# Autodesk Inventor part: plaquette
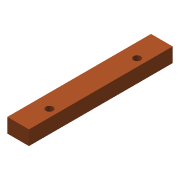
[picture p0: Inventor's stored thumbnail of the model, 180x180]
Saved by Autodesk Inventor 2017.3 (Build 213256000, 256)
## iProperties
Shininess: 20.0
Angle Display Precision: 2
Document Length Units: 11269
Document Angle Units: 11279
Document Time Units: 11290
Document Mass Units: 11283
Document Length Units Precision: 3
Document Angle Units Precision: 2
Created: 2002-04
Part Number: plaquette
Material: Générique
Document SubType Name: Modélisation
Designer: Administrateur
Density: 1 g/cm^3
Appearance: Orange (moyen)
Density: 0.0
Volumn: 0.0
Area: 0.0
PropertySet Name: Model Information
Control State: 0
Master: False
Checked Out: False
Author: Administrateur
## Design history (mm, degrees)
sketch "Esquisse1"
  geometry: L1 (-10, -0.25)-(-10, 99.25) reference; L2 (-25, 99.25)-(-10, 99.25) reference; L3 (-25, -0.25)-(-25, 99.25) reference; L4 (-10, -0.25)-(-25, -0.25) reference; L5 (-10, -0.25)-(-25, -0.25); L6 (-25, -0.25)-(-25, 99.25); L7 (-25, 99.25)-(-10, 99.25); L8 (-10, 99.25)-(-10, -0.25)
  constraints: 8 end point, 2 parallel, 1 horizontal, 1 perpendicular
extrude "Extrusion1" new body sketch "Esquisse1" distance "d0" = 10; taper "d1" = 0 deg
sketch "Esquisse2"
  geometry: C1 r 2.067 at (15.25, 79.8) reference; C2 r 2.067 at (15.25, 19.2) reference; C3 r 2.067 at (15.25, 19.2) reference; 2 further points
  constraints: 2 coincident
hole "Perçage1" sketch "Esquisse2" at (15.25, 79.8), (15.25, 19.2) diameter "d2" = 5; stored, may be unused: countersink angle "d6" = 82 deg, drill point angle "d8" = 118 deg; dims "d3" = 6, "d4" = 8.5, "d5" = 5.5, "d7" = 5
node "Solide1"
node "Corps solides"
node "Corps surfaciques"
node "Référence1"
